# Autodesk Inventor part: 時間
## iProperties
Created: 2001-06
Part Number: 時間
Document SubType Name: ﾓﾃﾞﾘﾝｸﾞ
Designer: Administrator
Control State: 0
Master: False
Checked Out: False
Shininess: 20.0
Length Units: 11269
Angle Units: 11279
Time Units: 11290
Mass Units: 11283
Length Display Precision: 3
Angle Display Precision: 2
Density: 0.0
Volumn: 0.0
Area: 0.0
PropertySet Name: Model Information
Author: Administrator
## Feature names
1. 押し出し1 [Extrusion]
